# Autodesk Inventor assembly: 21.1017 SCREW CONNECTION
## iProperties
Created: 2006-12
Part Number: 21.1017 SCREW CONNECTION
Document SubType Name: Assembly
Designer: Andy Moles
Mass: 32.0273 g
Surface Area: 31.3222 cm^2
Volume: 4.076 cm^3
Density: 7.85753 g/cm^3
Author: Andy Moles
